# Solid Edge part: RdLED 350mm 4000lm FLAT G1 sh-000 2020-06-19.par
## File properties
Author: sylwester.cabaj
Template: iso metric part.par
Last saved by: sylwester.cabaj
Revision: 3
Application: Solid Edge
Gęstość: 0,000 kg/m^3
Dokładność: 0,990
Username: sylwester.cabaj
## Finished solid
Body 1: solid body, 3878 faces, 10141 edges, 6693 vertices.
  Faces by surface: plane 3621, cylinder 123, spline 80, cone 26, torus 11, sphere 10, spun 7
  Edges by curve: line 9584, curve on surface 282, circle 165, ellipse 66, spline 38, intersection 6
Bounding box of the edges (mm; curved faces can reach further): 340.000 x 4.450 x 340.000, from (-170, -3.45, -170) to (170, 1, 170).
Cylindrical faces by radius (mm): R0.2 x39, R0.2002 x2, R0.2169 x3, R0.25 x12, R0.3 x2, R0.3373 x3, R0.4 x8, R0.4006 x2, R0.4008 x2, R0.525 x2, R0.6 x12, R1 x7, R1.0894 x2, R1.1 x14, R2.15 x9, R175 x4
Conical faces (half-angle, radius in mm at the cone's reference point): 0.5 deg R0.5056 x4, 0.5 deg R1.0082 x4, 1 deg R0.5511 x2, 10 deg R0.2132 x2, 10 deg R0.4132 x2, 18.4844 deg R1.0657 x4, 27.363 deg R0.6214 x2, 45 deg R0.575 x2, 45 deg R0.625 x4
Toroidal faces (ring radius, tube radius in mm): R0.1 r0.2 x1, R0.8 r0.2 x4, R0.8522 r0.3 x2, R0.9002 r0.2 x1, R0.9018 r0.2 x1, R1.3 r0.2 x2
Spherical faces by radius (mm): R0.2 x8, R0.6 x2
Planar faces by outward normal: +x 38, +y 8, +z 33, -x 29, -y 668, -z 33, oblique 2812
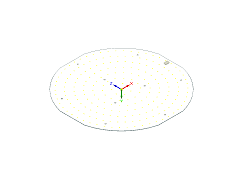
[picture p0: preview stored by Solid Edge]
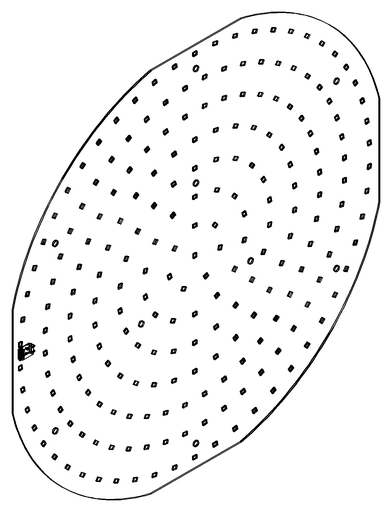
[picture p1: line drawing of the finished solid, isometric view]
